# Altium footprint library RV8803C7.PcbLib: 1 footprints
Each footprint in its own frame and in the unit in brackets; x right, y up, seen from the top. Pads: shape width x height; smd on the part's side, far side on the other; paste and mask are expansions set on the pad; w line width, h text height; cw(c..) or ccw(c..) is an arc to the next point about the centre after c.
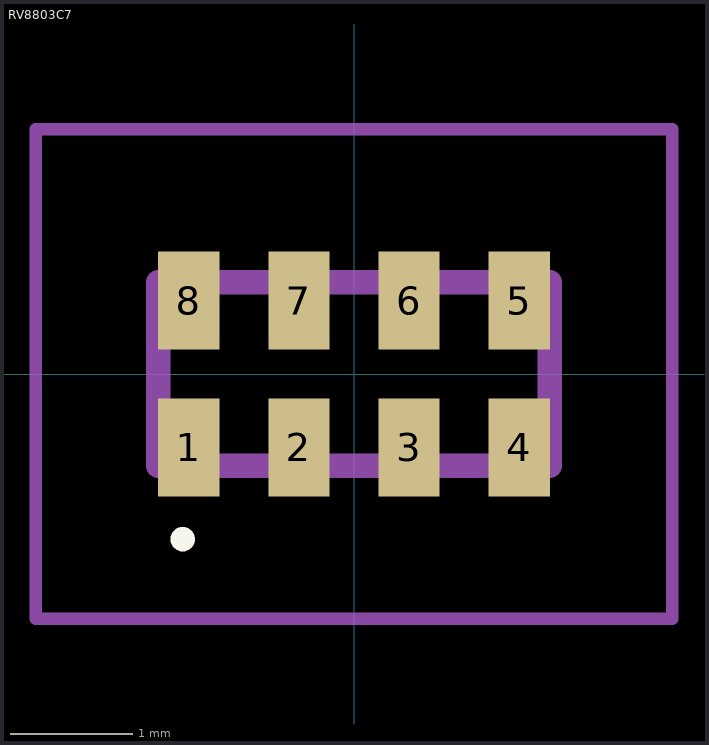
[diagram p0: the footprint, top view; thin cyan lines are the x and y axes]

## RV8803C7 [mm]
pads (8):
  rect 0.5x0.8 smd: 1(-1.35,-0.6) 2(-0.45,-0.6) 3(0.45,-0.6) 4(1.35,-0.6) 5(1.35,0.6) 6(0.45,0.6) 7(-0.45,0.6) 8(-1.35,0.6)
Top Overlay:
  lines w0.1: -1.4,-1.4 -1.4,-1.4 ; -1.4,-1.4 ccw(c-1.4,-1.35) -1.4,-1.3 ; -1.4,-1.4 cw(c-1.4,-1.35) -1.4,-1.3 ; -1.4,-1.3 -1.4,-1.3
Mechanical 15:
  lines w0.2: -1.6,-0.75 1.6,-0.75 1.6,0.75 -1.6,0.75 -1.6,-0.75
Mechanical 20:
  lines w0.1: -2.6,-2 2.6,-2 2.6,2 -2.6,2 -2.6,-2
